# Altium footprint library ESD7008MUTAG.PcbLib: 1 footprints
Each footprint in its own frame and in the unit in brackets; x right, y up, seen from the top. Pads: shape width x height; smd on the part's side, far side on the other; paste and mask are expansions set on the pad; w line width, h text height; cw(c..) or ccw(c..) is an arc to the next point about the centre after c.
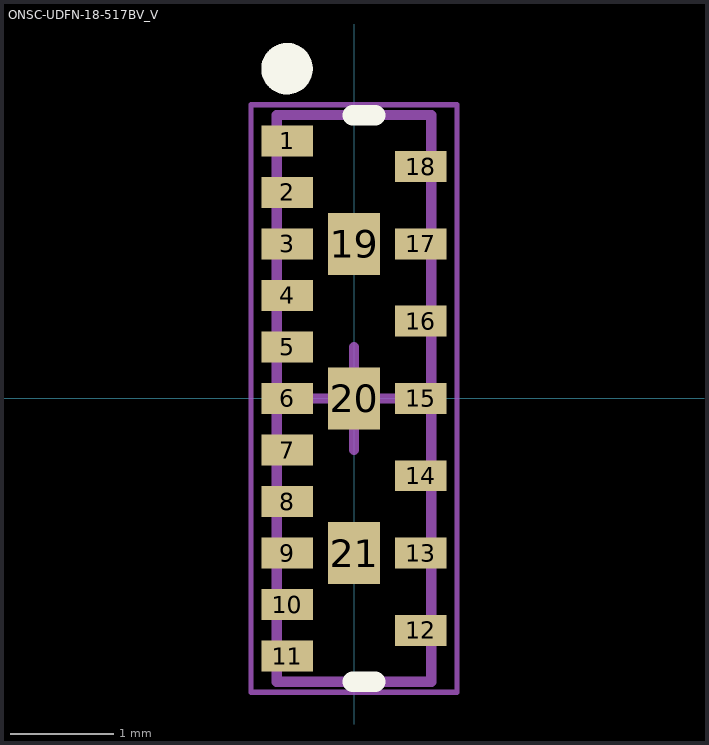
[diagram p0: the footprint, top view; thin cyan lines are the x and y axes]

## ONSC-UDFN-18-517BV_V [mm] "SON, 18-Leads, Body 5.5x1.5mm"
height 0.55
pads (21):
  rect 0.5x0.3 smd: 1(-0.65,2.5) 2(-0.65,2) 3(-0.65,1.5) 4(-0.65,1) 5(-0.65,0.5) 6(-0.65,0) 7(-0.65,-0.5) 8(-0.65,-1) 9(-0.65,-1.5) 10(-0.65,-2) 11(-0.65,-2.5) 12(0.65,-2.25) 13(0.65,-1.5) 14(0.65,-0.75) 15(0.65,0) 16(0.65,0.75) 17(0.65,1.5) 18(0.65,2.25)
  rect 0.5x0.6 smd: 19(0,1.5) 20(0,0) 21(0,-1.5)
Top Overlay:
  circle w0.25: c-0.65,3.2 r0.125
  lines w0.2: -0.013,-2.75 0.206,-2.75 ; -0.013,2.75 0.206,2.75
Mechanical 13:
  lines w0.1: -0.75,-2.75 -0.75,2.75 0.75,2.75 0.75,-2.75 -0.75,-2.75
Mechanical 15:
  lines w0.05: -1,-2.85 -1,2.85 1,2.85 1,-2.85 -1,-2.85
  lines w0.1: -0.5,0 0.5,0 ; 0,-0.5 0,0.5
3D body: height 0.55, standoff 0, extent -0.75,-2.75 0.75,2.75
